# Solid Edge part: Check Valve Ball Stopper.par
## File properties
Title: Check Valve Ball Stopper
Author: Dan
Template: Normal.par
Last saved by: Dan
Revision: 11
Application: Solid Edge
Density: 0 kg/mm^3
Accuracy: 0.99
Document Number: P52-019
Project Name: Piston Pump P52
Material: steel
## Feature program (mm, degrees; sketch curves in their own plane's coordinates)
sketch for "unnamed Protrusion 1" plane through (0, 0, 0) normal (1, 0, 0) x-axis (0, 1, 0)
  circle centre (0, 0) radius 5
extrude "unnamed Protrusion 1" add finite 6 along -normal
sketch for "ExtrudedProtrusion_2" plane through (0, 0, 0) normal (1, 0, 0) x-axis (0, 1, 0)
  circle centre (0, 0) radius 2.5
extrude "ExtrudedProtrusion_2" add finite 4.5 along +normal
chamfer "Chamfer_1" setback 0.5
sketch for "Hole_1" plane through (0, 0, 0) normal (0, 0, 1) x-axis (1, 0, 0)
  hole centre (-2.9, 0) bore radius 1.6
hole "Hole_1" diameter 3.2 through
fillet "Round_1" radius 0.8
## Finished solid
Body 1: solid body, 10 faces, 10 edges, 0 vertices.
  Faces by surface: cone 3, cylinder 3, plane 3, torus 1
  Edges by curve: circle 8, intersection 2
Bounding box of the edges (mm; curved faces can reach further): 10.500 x 10.000 x 10.000, from (-6, -5, -5) to (4.5, 5, 5).
Cylindrical faces by radius (mm): R1.6 x1, R2.5 x1, R5 x1
Conical faces (half-angle, radius in mm at the cone's reference point): 45 deg R2.5 x1, 45 deg R4.5 x1, 45 deg R5 x1
Toroidal faces (ring radius, tube radius in mm): R3.3 r0.8 x1
Planar faces by outward normal: +x 2, -x 1
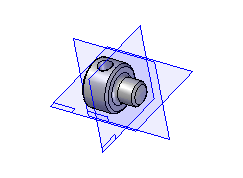
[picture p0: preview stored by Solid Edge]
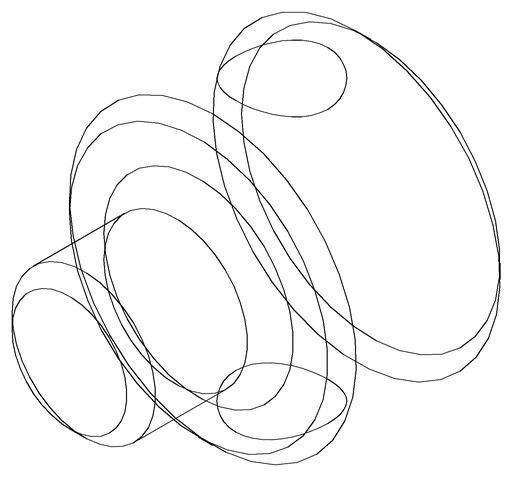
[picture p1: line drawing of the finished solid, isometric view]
